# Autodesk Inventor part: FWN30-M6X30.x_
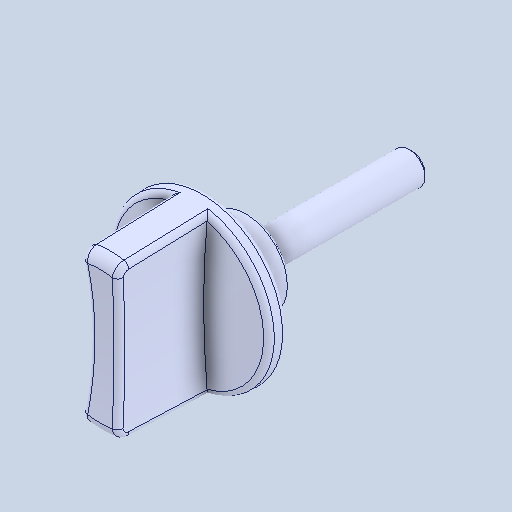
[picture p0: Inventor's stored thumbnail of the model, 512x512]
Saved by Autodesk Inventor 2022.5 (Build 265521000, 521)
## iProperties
Created: 2024-05
Part Number: FWN30-M6X30.x_
Material: 一般
Document SubType Name: Modeling
Designer: ImaoCorp
Density: 1 g/cm^3
Appearance: 既定
Author: ImaoCorp
Sending System: SOLIDWORKS 2022-2022290
MC: AMD64
MC_MODEL: Intel64 Family 6 Model 60 Stepping 3, GenuineIntel
OS: Windows_NT
FRU: Parasolid Version 33.1, build 260,  4-25-2022
FORMAT: text
GUISE: transmit
KEY: FILEFWN30-M6X30.x_t
DATE: Mon May 20 16:40:35 2024
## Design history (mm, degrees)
feature "Base1"
node "ソリッド1"
